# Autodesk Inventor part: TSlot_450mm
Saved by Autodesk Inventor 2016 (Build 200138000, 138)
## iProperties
Created: 2016-01
Part Number: TSlot_450mm
Material: Generic
Document SubType Name: Modeling
Designer: John
Density: 1 g/cm^3
Appearance: Default
Author: John
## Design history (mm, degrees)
feature "SOLID1"
body "Solid1"
